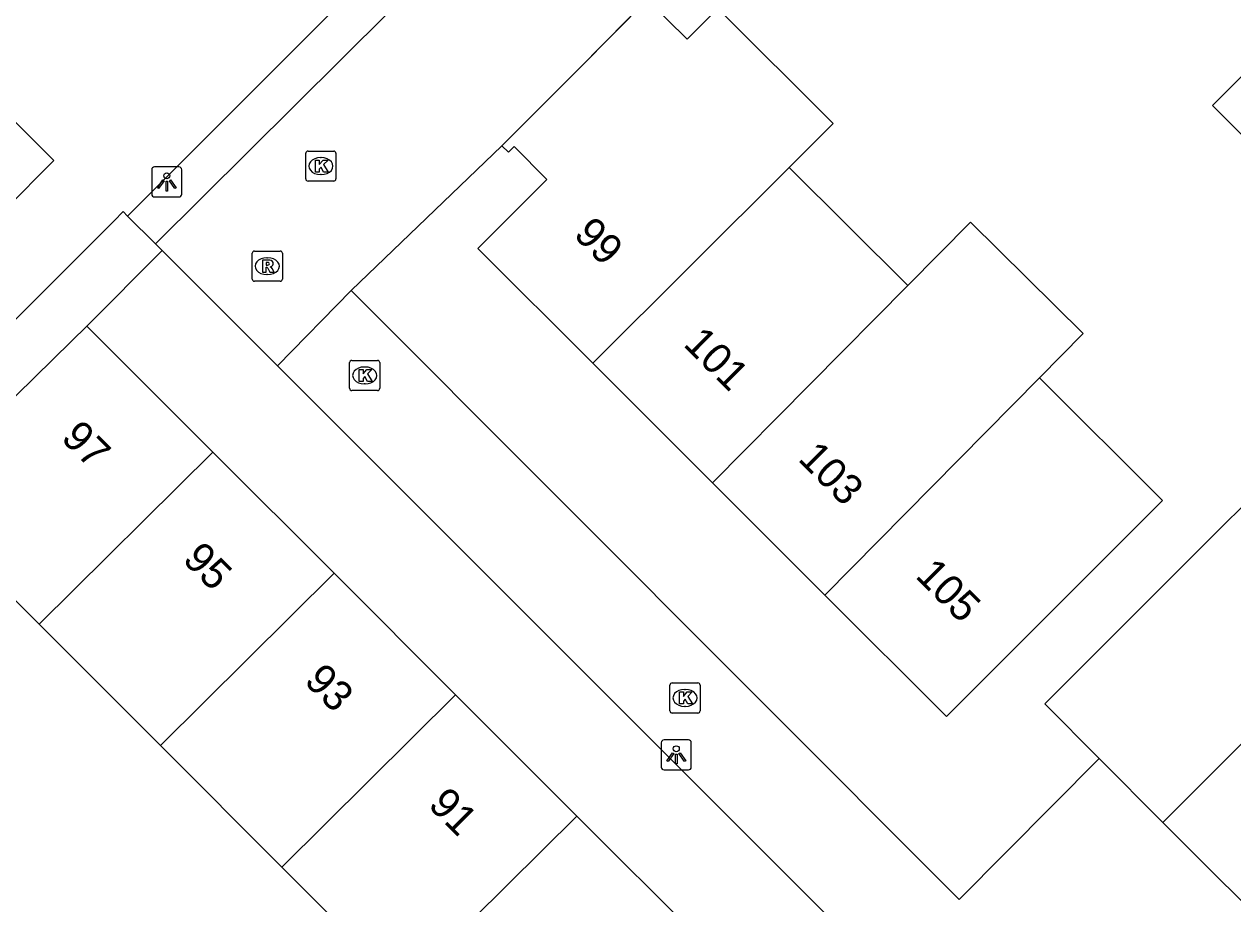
# Model space of a CAD drawing. Extents: x 159961 to 160856, y 382704 to 383353.
# Drawn here: x 160157.81 to 160197.89, y 383187.58 to 383216.75 of the extents above; entities that cross this region are included whole.
import ezdxf

# ---------------------------------------------------------------- set-up
doc = ezdxf.new("R2010")
doc.units = 0
for name, color, linetype in [('IMGEO_Kolk', 7, 'Continuous'), ('IMGEO_Lichtpunt', 7, 'Continuous'), ('IMGEO_Muur', 7, 'Continuous'), ('IMGEO_Pand', 7, 'Continuous'), ('IMGEO_Pand_nummerreeks', 7, 'Continuous'), ('IMGEO_Parkeervlak_open', 7, 'Continuous'), ('IMGEO_Rijbaan_lokaal_open', 7, 'Continuous'), ('IMGEO_Rioolput', 7, 'Continuous'), ('IMGEO_Voetpad_open', 7, 'Continuous')]:
    doc.layers.add(name, color=color, linetype=linetype)

msp = doc.modelspace()

# ---------------------------------------------------------------- linework, layer by layer
at = {"layer": 'IMGEO_Kolk'}
for p, q in [((160167.151, 383211.615), (160167.151, 383212.467)), ((160167.226, 383212.541), (160168.078, 383212.541)), ((160167.639, 383212.321), (160167.664, 383212.321)), ((160168.152, 383212.467), (160168.152, 383211.615)), ((160168.078, 383211.541), (160167.226, 383211.541)), ((160167.662, 383211.761), (160167.637, 383211.761)), ((160168.605, 383204.674), (160168.605, 383205.526)), ((160168.68, 383205.6), (160169.532, 383205.6)), ((160169.606, 383205.526), (160169.606, 383204.674)), ((160169.093, 383205.38), (160169.118, 383205.38)), ((160169.116, 383204.82), (160169.091, 383204.82)), ((160169.532, 383204.6), (160168.68, 383204.6)), ((160179.225, 383193.982), (160179.225, 383194.834)), ((160179.3, 383194.908), (160180.152, 383194.908)), ((160179.713, 383194.688), (160179.738, 383194.688)), ((160180.226, 383194.834), (160180.226, 383193.982)), ((160180.152, 383193.908), (160179.3, 383193.908)), ((160179.736, 383194.128), (160179.711, 383194.128))]:
    msp.add_line(p, q, dxfattribs=at)
for points in [[(160167.151, 383211.615), (160167.151, 383212.467)], [(160167.226, 383212.541), (160168.078, 383212.541)], [(160168.152, 383212.467), (160168.152, 383211.615)], [(160167.472, 383212.241), (160167.595, 383212.241), (160167.595, 383212.09), (160167.725, 383212.241), (160167.889, 383212.241), (160167.743, 383212.09), (160167.896, 383211.841), (160167.744, 383211.841), (160167.659, 383212.005), (160167.595, 383211.938), (160167.595, 383211.841), (160167.472, 383211.841), (160167.472, 383212.241)], [(160168.078, 383211.541), (160167.226, 383211.541)], [(160168.605, 383204.674), (160168.605, 383205.526)], [(160168.68, 383205.6), (160169.532, 383205.6)], [(160169.606, 383205.526), (160169.606, 383204.674)], [(160168.926, 383205.3), (160169.049, 383205.3), (160169.049, 383205.149), (160169.179, 383205.3), (160169.343, 383205.3), (160169.197, 383205.149), (160169.35, 383204.9), (160169.198, 383204.9), (160169.113, 383205.064), (160169.049, 383204.997), (160169.049, 383204.9), (160168.926, 383204.9), (160168.926, 383205.3)], [(160169.532, 383204.6), (160168.68, 383204.6)], [(160179.225, 383193.982), (160179.225, 383194.834)], [(160179.3, 383194.908), (160180.152, 383194.908)], [(160180.226, 383194.834), (160180.226, 383193.982)], [(160179.546, 383194.608), (160179.669, 383194.608), (160179.669, 383194.457), (160179.799, 383194.608), (160179.963, 383194.608), (160179.817, 383194.457), (160179.97, 383194.208), (160179.818, 383194.208), (160179.733, 383194.372), (160179.669, 383194.305), (160179.669, 383194.208), (160179.546, 383194.208), (160179.546, 383194.608)], [(160180.152, 383193.908), (160179.3, 383193.908)]]:
    msp.add_lwpolyline(points, dxfattribs=at)
for centre, start, end in [((160167.228, 383212.465), 91.552, 178.448), ((160167.228, 383212.465), 91.552, 178.448), ((160168.076, 383212.465), 1.552, 88.448), ((160168.076, 383212.465), 1.552, 88.448), ((160167.228, 383211.617), 181.552, 268.448), ((160167.228, 383211.617), 181.552, 268.448), ((160168.076, 383211.617), 271.552, 358.448), ((160168.076, 383211.617), 271.552, 358.448), ((160168.682, 383205.524), 91.552, 178.448), ((160168.682, 383205.524), 91.552, 178.448), ((160169.53, 383205.524), 1.552, 88.448), ((160169.53, 383205.524), 1.552, 88.448), ((160168.682, 383204.676), 181.552, 268.448), ((160168.682, 383204.676), 181.552, 268.448), ((160169.53, 383204.676), 271.552, 358.448), ((160169.53, 383204.676), 271.552, 358.448), ((160179.302, 383194.832), 91.552, 178.448), ((160179.302, 383194.832), 91.552, 178.448), ((160180.15, 383194.832), 1.552, 88.448), ((160180.15, 383194.832), 1.552, 88.448), ((160179.302, 383193.984), 181.552, 268.448), ((160179.302, 383193.984), 181.552, 268.448), ((160180.15, 383193.984), 271.552, 358.448), ((160180.15, 383193.984), 271.552, 358.448)]:
    msp.add_arc(centre, 0.0765, start, end, dxfattribs=at)
for centre, major_axis, ratio, start_param, end_param in [((160167.638, 383212.041), (-0.387, 0.002), 0.722429, 4.712389, 7.853982), ((160167.663, 383212.041), (-0.39, 0.002), 0.717154, 1.570796, 4.712389), ((160169.092, 383205.1), (-0.387, 0.002), 0.722429, 4.712389, 7.853982), ((160169.117, 383205.1), (-0.39, 0.002), 0.717154, 1.570796, 4.712389), ((160179.712, 383194.408), (-0.387, 0.002), 0.722429, 4.712389, 7.853982), ((160179.737, 383194.408), (-0.39, 0.002), 0.717154, 1.570796, 4.712389)]:
    msp.add_ellipse(centre, major_axis=major_axis, ratio=ratio, start_param=start_param, end_param=end_param, dxfattribs=at)
at = {"layer": 'IMGEO_Lichtpunt'}
for p, q in [((160162.043, 383211.921), (160162.043, 383211.114)), ((160162.043, 383211.921), (160162.043, 383211.114)), ((160162.945, 383212.016), (160162.137, 383212.016)), ((160162.945, 383212.016), (160162.137, 383212.016)), ((160163.039, 383211.114), (160163.039, 383211.921)), ((160163.039, 383211.114), (160163.039, 383211.921)), ((160162.137, 383211.02), (160162.945, 383211.02)), ((160162.137, 383211.02), (160162.945, 383211.02)), ((160178.937, 383192.924), (160178.937, 383192.117)), ((160178.937, 383192.924), (160178.937, 383192.117)), ((160179.839, 383193.019), (160179.031, 383193.019)), ((160179.839, 383193.019), (160179.031, 383193.019)), ((160179.933, 383192.117), (160179.933, 383192.924)), ((160179.933, 383192.117), (160179.933, 383192.924)), ((160179.031, 383192.023), (160179.839, 383192.023)), ((160179.031, 383192.023), (160179.839, 383192.023))]:
    msp.add_line(p, q, dxfattribs=at)
for points in [[(160162.417, 383211.585), (160162.456, 383211.557), (160162.268, 383211.295), (160162.23, 383211.322), (160162.417, 383211.585)], [(160162.519, 383211.537), (160162.566, 383211.537), (160162.566, 383211.215), (160162.519, 383211.215), (160162.519, 383211.537)], [(160162.629, 383211.557), (160162.667, 383211.584), (160162.854, 383211.322), (160162.815, 383211.294), (160162.629, 383211.557)], [(160179.311, 383192.588), (160179.35, 383192.56), (160179.162, 383192.298), (160179.124, 383192.325), (160179.311, 383192.588)], [(160179.413, 383192.54), (160179.46, 383192.54), (160179.46, 383192.218), (160179.413, 383192.218), (160179.413, 383192.54)], [(160179.523, 383192.56), (160179.561, 383192.587), (160179.748, 383192.325), (160179.709, 383192.297), (160179.523, 383192.56)]]:
    msp.add_lwpolyline(points, dxfattribs=at)
for centre in [(160162.542, 383211.719), (160179.436, 383192.722)]:
    msp.add_circle(centre, 0.0994, dxfattribs=at)
for centre, start, end in [((160162.137, 383211.921), 90, 180), ((160162.137, 383211.921), 90, 180), ((160162.945, 383211.921), 0, 90), ((160162.945, 383211.921), 0, 90), ((160162.137, 383211.114), 180, 270), ((160162.137, 383211.114), 180, 270), ((160162.945, 383211.114), 270, 0), ((160162.945, 383211.114), 270, 360), ((160179.031, 383192.924), 90, 180), ((160179.031, 383192.924), 90, 180), ((160179.839, 383192.924), 0, 90), ((160179.839, 383192.924), 0, 90), ((160179.031, 383192.117), 180, 270), ((160179.031, 383192.117), 180, 270), ((160179.839, 383192.117), 270, 0), ((160179.839, 383192.117), 270, 360)]:
    msp.add_arc(centre, 0.0946, start, end, dxfattribs=at)
at = {"layer": 'IMGEO_Muur'}
for points in [[(160176.228, 383215.286), (160186.689, 383225.914)], [(160161.242, 383210.384), (160167.442, 383216.579)]]:
    msp.add_lwpolyline(points, dxfattribs=at)
at = {"layer": 'IMGEO_Pand'}
for points in [[(160200.167, 383223.186), (160196.218, 383219.316), (160198.288, 383217.242), (160199.347, 383216.181), (160197.211, 383214.048), (160200.402, 383210.854), (160202.519, 383212.968), (160204.728, 383210.755), (160208.63, 383214.651)], [(160173.656, 383212.71), (160176.228, 383215.286), (160178.473, 383217.566)], [(160178.473, 383217.566), (160179.791, 383216.25), (160180.81, 383217.27), (160184.638, 383213.451), (160183.181, 383211.999)], [(160156.688, 383214.331), (160158.8, 383212.222), (160157.176, 383210.596), (160155.065, 383212.704)], [(160176.664, 383205.505), (160172.857, 383209.307), (160175.147, 383211.6), (160174.058, 383212.689), (160173.868, 383212.498), (160173.656, 383212.71)], [(160183.181, 383211.999), (160176.664, 383205.505)], [(160183.181, 383211.999), (160187.108, 383208.077)], [(160191.482, 383205.026), (160192.923, 383206.486), (160189.19, 383210.181), (160187.108, 383208.077)], [(160187.108, 383208.077), (160180.637, 383201.538)], [(160154.106, 383201.066), (160156.319, 383203.236), (160159.389, 383206.239), (160159.888, 383206.737)], [(160159.888, 383206.737), (160164.071, 383202.556)], [(160180.637, 383201.538), (160176.664, 383205.505)], [(160184.364, 383197.818), (160188.398, 383193.789), (160195.556, 383200.958), (160191.482, 383205.026)], [(160191.482, 383205.026), (160184.364, 383197.818)], [(160164.071, 383202.556), (160158.313, 383196.852)], [(160164.071, 383202.556), (160168.088, 383198.54)], [(160180.637, 383201.538), (160184.364, 383197.818)], [(160158.313, 383196.852), (160154.106, 383201.066)], [(160162.329, 383192.831), (160168.088, 383198.54)], [(160168.088, 383198.54), (160172.12, 383194.509)], [(160162.329, 383192.831), (160158.313, 383196.852)], [(160166.358, 383188.795), (160172.12, 383194.509)], [(160172.12, 383194.509), (160176.138, 383190.493)], [(160166.358, 383188.795), (160162.329, 383192.831)], [(160176.138, 383190.493), (160170.372, 383184.774)], [(160176.138, 383190.493), (160180.171, 383186.462)], [(160170.372, 383184.774), (160166.358, 383188.795)]]:
    msp.add_lwpolyline(points, dxfattribs=at)
at = {"layer": 'IMGEO_Parkeervlak_open'}
msp.add_lwpolyline([(160204.129, 383206.68), (160191.651, 383194.212), (160193.455, 383192.399)], dxfattribs=at)
at = {"layer": 'IMGEO_Rijbaan_lokaal_open'}
for points in [[(160177.606, 383224.807), (160162.167, 383209.46)], [(160168.655, 383207.917), (160173.656, 383212.71)], [(160162.167, 383209.46), (160162.389, 383209.238)], [(160162.389, 383209.238), (160166.213, 383205.414)], [(160166.213, 383205.414), (160168.655, 383207.917)], [(160195.571, 383190.282), (160202.907, 383197.612), (160208.066, 383202.745)], [(160207.355, 383190.927), (160199.831, 383186.018), (160195.571, 383190.282)]]:
    msp.add_lwpolyline(points, dxfattribs=at)
at = {"layer": 'IMGEO_Rioolput'}
for p, q in [((160165.374, 383208.297), (160165.374, 383209.149)), ((160165.449, 383209.223), (160166.301, 383209.223)), ((160166.375, 383209.149), (160166.375, 383208.297)), ((160165.862, 383209.003), (160165.887, 383209.003)), ((160165.885, 383208.443), (160165.86, 383208.443)), ((160166.301, 383208.223), (160165.449, 383208.223))]:
    msp.add_line(p, q, dxfattribs=at)
for points in [[(160165.374, 383208.297), (160165.374, 383209.149)], [(160165.449, 383209.223), (160166.301, 383209.223)], [(160166.375, 383209.149), (160166.375, 383208.297)], [(160165.963, 383208.921), (160165.711, 383208.923), (160165.711, 383208.523)], [(160165.711, 383208.523), (160165.835, 383208.523), (160165.835, 383208.685), (160165.846, 383208.685)], [(160165.889, 383208.842), (160165.835, 383208.842), (160165.835, 383208.761)], [(160165.835, 383208.761), (160165.887, 383208.761)], [(160165.893, 383208.656), (160165.964, 383208.523), (160166.104, 383208.523), (160166.039, 383208.649)], [(160166.301, 383208.223), (160165.449, 383208.223)]]:
    msp.add_lwpolyline(points, dxfattribs=at)
for centre, radius, start, end in [((160165.451, 383209.147), 0.0765, 91.552, 178.448), ((160165.451, 383209.147), 0.0765, 91.552, 178.448), ((160166.299, 383209.147), 0.0765, 1.552, 88.448), ((160166.299, 383209.147), 0.0765, 1.552, 88.448), ((160165.845, 383208.632), 0.0533, 26.0293, 88.6989), ((160165.871, 383208.95), 0.19, 274.7715, 282.9687), ((160165.895, 383208.746), 0.0964, 77.0061, 93.1865), ((160165.909, 383208.803), 0.0378, 276.6634, 79.6772), ((160165.962, 383208.811), 0.109, 350.3612, 89.416), ((160165.96, 383208.811), 0.112, 277.5842, 350.9817), ((160165.944, 383208.596), 0.108, 29.5134, 73.7905), ((160165.451, 383208.299), 0.0765, 181.552, 268.448), ((160165.451, 383208.299), 0.0765, 181.552, 268.448), ((160166.299, 383208.299), 0.0765, 271.552, 358.448), ((160166.299, 383208.299), 0.0765, 271.552, 358.448)]:
    msp.add_arc(centre, radius, start, end, dxfattribs=at)
for centre, major_axis, ratio, start_param, end_param in [((160165.861, 383208.723), (-0.387, 0.002), 0.722429, 4.712389, 7.853982), ((160165.886, 383208.723), (-0.39, 0.002), 0.717154, 1.570796, 4.712389)]:
    msp.add_ellipse(centre, major_axis=major_axis, ratio=ratio, start_param=start_param, end_param=end_param, dxfattribs=at)
at = {"layer": 'IMGEO_Voetpad_open'}
for points in [[(160161.242, 383210.384), (160167.442, 383216.579), (160177.527, 383226.652)], [(160156.4, 383205.844), (160159.17, 383208.605), (160160.794, 383210.231), (160161.094, 383210.532), (160161.242, 383210.384)], [(160162.167, 383209.46), (160161.242, 383210.384)], [(160162.389, 383209.238), (160159.888, 383206.737)], [(160193.455, 383192.399), (160188.819, 383187.729), (160168.655, 383207.917)], [(160234.488, 383134.119), (160238.639, 383138.271), (160238.921, 383140.771), (160225.599, 383160.881), (160219.57, 383156.892), (160205.046, 383171.448), (160202.606, 383169.025), (160198.736, 383172.895), (160192.747, 383178.882), (160186.369, 383185.261), (160166.213, 383205.414)], [(160193.455, 383192.399), (160195.571, 383190.282)]]:
    msp.add_lwpolyline(points, dxfattribs=at)

# ---------------------------------------------------------------- texts
at = {"layer": 'IMGEO_Pand_nummerreeks'}
for s, rotation, p in [('99', 315.04, (160175.995, 383209.734)), ('101', 315.0424, (160179.636, 383206.1)), ('97', 315.0114, (160159, 383202.988)), ('103', 315.0424, (160183.44, 383202.301)), ('95', 315.0114, (160163.03, 383198.959)), ('105', 315.0424, (160187.325, 383198.422)), ('93', 315.0114, (160167.061, 383194.93)), ('91', 315.0114, (160171.171, 383190.822))]:
    msp.add_text(s, height=1, rotation=rotation, dxfattribs=at).set_placement(p)

doc.saveas('drawing.dxf')
